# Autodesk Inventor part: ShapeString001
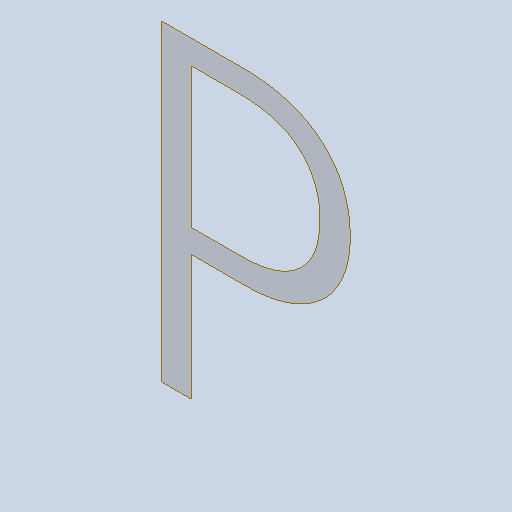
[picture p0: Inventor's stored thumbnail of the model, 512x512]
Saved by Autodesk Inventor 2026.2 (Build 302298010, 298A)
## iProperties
Created: 2026-10
Part Number: ShapeString001
Material: Générique
Document SubType Name: Modeling
Designer: mel
Density: 1 g/cm^3
Appearance: Par défaut
Author: mel
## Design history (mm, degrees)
feature "Composite1"
body "Srf1"
